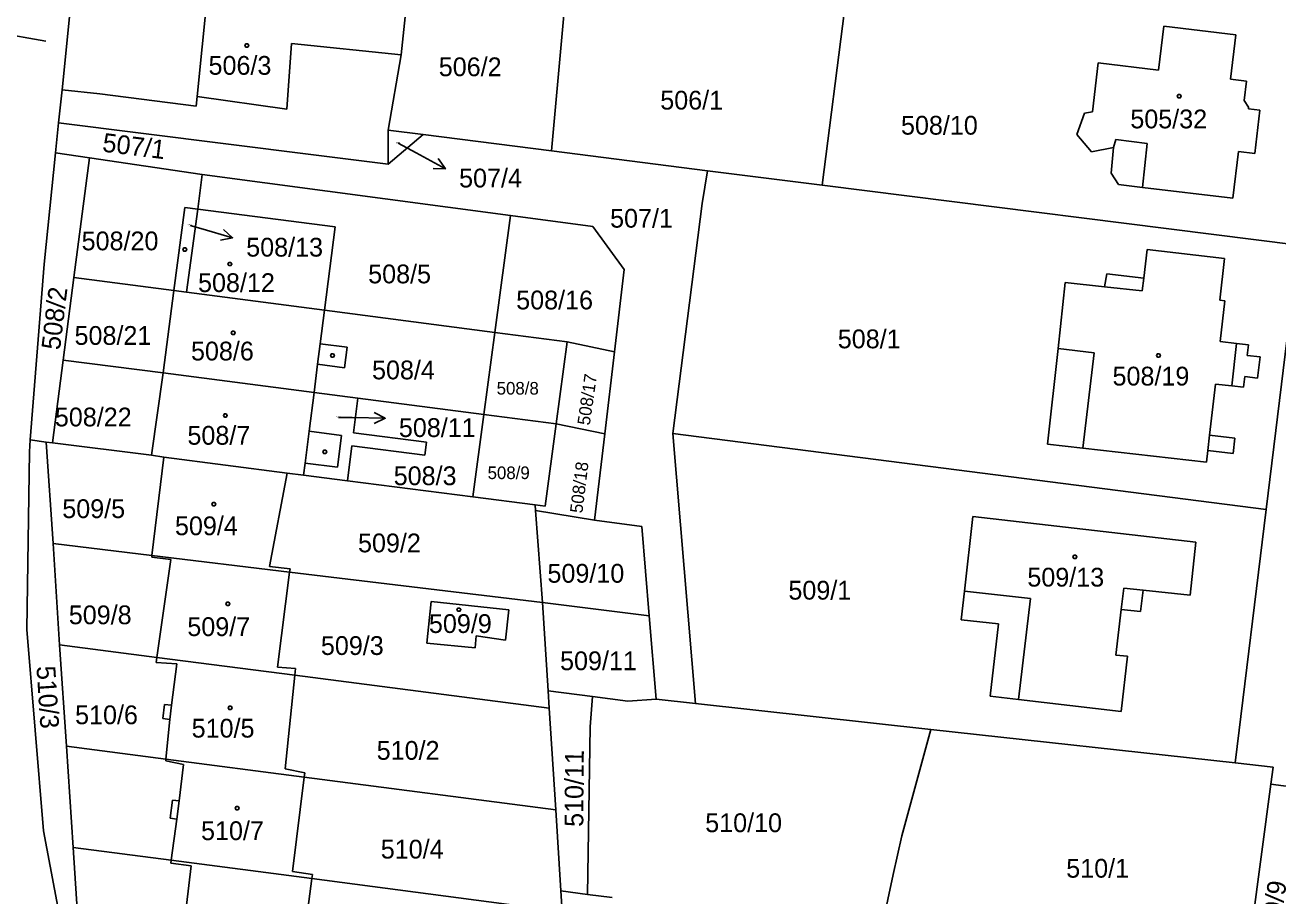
# Model space of a CAD drawing. Extents: x -639590 to -639298, y -1193269 to -1192863.
# Drawn here: x -639509.2 to -639395.8, y -1192995.4 to -1192916.5 of the extents above; entities that cross this region are included whole.
import ezdxf

# ---------------------------------------------------------------- set-up
doc = ezdxf.new("R2010")
doc.units = 0
for name, color, linetype in [('Vrstva 1', 7, 'Continuous'), ('Vrstva 2', 7, 'Continuous'), ('Vrstva 25', 7, 'Continuous'), ('Vrstva 4', 7, 'Continuous'), ('Vrstva 5', 7, 'Continuous'), ('Vrstva 7', 7, 'Continuous')]:
    doc.layers.add(name, color=color, linetype=linetype)

msp = doc.modelspace()

# ---------------------------------------------------------------- linework, layer by layer
at = {"layer": 'Vrstva 1'}
for p, q in [((-639504.16, -1192906.23), (-639505.82, -1192922.39)), ((-639461.52, -1192927.91), (-639460.05, -1192911.94)), ((-639492.68, -1192913.98), (-639493.6, -1192922.99)), ((-639475.12, -1192919.21), (-639474.65, -1192914.63)), ((-639434.99, -1192915.19), (-639437.01, -1192931.02)), ((-639406.1, -1192916.63), (-639406.58, -1192920.61)), ((-639399.58, -1192917.41), (-639406.1, -1192916.63)), ((-639400.06, -1192921.43), (-639399.58, -1192917.41)), ((-639475.12, -1192919.21), (-639476.29, -1192926.03)), ((-639412.03, -1192919.95), (-639412.54, -1192924.38)), ((-639406.58, -1192920.61), (-639412.03, -1192919.95)), ((-639398.59, -1192921.61), (-639400.06, -1192921.43)), ((-639398.8, -1192923.34), (-639398.59, -1192921.61)), ((-639505.82, -1192922.39), (-639506.13, -1192925.38)), ((-639505.82, -1192922.39), (-639502.41, -1192922.75)), ((-639502.41, -1192922.75), (-639493.69, -1192923.85)), ((-639493.69, -1192923.85), (-639493.6, -1192922.99)), ((-639398.41, -1192923.95), (-639398.8, -1192923.34)), ((-639398.43, -1192924.1), (-639398.41, -1192923.95)), ((-639413.28, -1192924.5), (-639413.96, -1192926.43)), ((-639412.54, -1192924.38), (-639413.28, -1192924.5)), ((-639397.39, -1192924.22), (-639398.43, -1192924.1)), ((-639397.86, -1192928.14), (-639397.39, -1192924.22)), ((-639506.13, -1192925.38), (-639506.41, -1192928.09)), ((-639506.13, -1192925.38), (-639483.29, -1192928.23)), ((-639476.29, -1192926.03), (-639476.3, -1192929.1)), ((-639476.29, -1192926.03), (-639473.13, -1192926.43)), ((-639476.3, -1192929.1), (-639473.13, -1192926.43)), ((-639473.13, -1192926.43), (-639461.52, -1192927.91)), ((-639413.96, -1192926.43), (-639412.64, -1192928)), ((-639506.41, -1192928.09), (-639507.43, -1192938.15)), ((-639506.41, -1192928.09), (-639503.33, -1192928.54)), ((-639483.29, -1192928.23), (-639476.3, -1192929.1)), ((-639461.52, -1192927.91), (-639447.4, -1192929.71)), ((-639412.64, -1192928), (-639410.64, -1192927.59)), ((-639410.64, -1192927.59), (-639410.84, -1192929.94)), ((-639399.85, -1192932.18), (-639399.34, -1192927.96)), ((-639399.34, -1192927.96), (-639397.86, -1192928.14)), ((-639503.33, -1192928.54), (-639504.74, -1192939.37)), ((-639493.13, -1192930.04), (-639503.33, -1192928.54)), ((-639493.54, -1192933.18), (-639493.13, -1192930.04)), ((-639493.13, -1192930.04), (-639465.22, -1192933.76)), ((-639447.88, -1192932.66), (-639447.4, -1192929.71)), ((-639437.01, -1192931.02), (-639447.4, -1192929.71)), ((-639410.84, -1192929.94), (-639410.19, -1192930.95)), ((-639393.89, -1192936.45), (-639437.01, -1192931.02)), ((-639410.19, -1192930.95), (-639408.01, -1192931.21)), ((-639408.01, -1192931.21), (-639399.85, -1192932.18)), ((-639495.71, -1192940.54), (-639494.72, -1192933.03)), ((-639494.72, -1192933.03), (-639493.54, -1192933.18)), ((-639450.53, -1192953.5), (-639447.88, -1192932.66)), ((-639494.57, -1192940.69), (-639493.54, -1192933.18)), ((-639493.54, -1192933.18), (-639481.11, -1192934.79)), ((-639466.65, -1192944.34), (-639465.22, -1192933.76)), ((-639465.22, -1192933.76), (-639457.78, -1192934.75)), ((-639481.11, -1192934.79), (-639482.07, -1192942.33)), ((-639457.78, -1192934.75), (-639454.93, -1192938.64)), ((-639393.89, -1192936.45), (-639396.82, -1192960.36)), ((-639407.58, -1192936.84), (-639407.89, -1192939.43)), ((-639400.58, -1192937.64), (-639407.58, -1192936.84)), ((-639507.43, -1192938.15), (-639508.7, -1192954.08)), ((-639454.93, -1192938.64), (-639455.81, -1192946.09)), ((-639401.01, -1192941.42), (-639400.58, -1192937.64)), ((-639504.74, -1192939.37), (-639505.71, -1192946.84)), ((-639504.74, -1192939.37), (-639495.71, -1192940.54)), ((-639415.02, -1192939.83), (-639415.66, -1192945.81)), ((-639411.45, -1192940.22), (-639415.02, -1192939.83)), ((-639411.26, -1192939.05), (-639411.45, -1192940.22)), ((-639407.89, -1192939.43), (-639411.26, -1192939.05)), ((-639496.66, -1192948), (-639495.71, -1192940.54)), ((-639495.71, -1192940.54), (-639494.57, -1192940.69)), ((-639494.57, -1192940.69), (-639482.07, -1192942.33)), ((-639400.57, -1192941.47), (-639401.01, -1192941.42)), ((-639400.99, -1192945.17), (-639400.57, -1192941.47)), ((-639482.07, -1192942.33), (-639482.46, -1192945.37)), ((-639482.07, -1192942.33), (-639466.65, -1192944.34)), ((-639467.65, -1192951.78), (-639466.65, -1192944.34)), ((-639460.11, -1192945.19), (-639466.65, -1192944.34)), ((-639480, -1192945.68), (-639482.46, -1192945.37)), ((-639461.1, -1192952.63), (-639460.11, -1192945.19)), ((-639460.11, -1192945.19), (-639455.81, -1192946.09)), ((-639399.5, -1192945.34), (-639400.99, -1192945.17)), ((-639398.43, -1192945.46), (-639399.5, -1192945.34)), ((-639398.54, -1192946.42), (-639398.43, -1192945.46)), ((-639480, -1192945.68), (-639480.24, -1192947.55)), ((-639455.81, -1192946.09), (-639456.69, -1192953.53)), ((-639415.66, -1192945.81), (-639416.62, -1192954.46)), ((-639397.38, -1192946.56), (-639398.54, -1192946.42)), ((-639397.6, -1192948.47), (-639397.38, -1192946.56)), ((-639505.71, -1192946.84), (-639506.68, -1192954.34)), ((-639505.71, -1192946.84), (-639496.66, -1192948)), ((-639482.69, -1192947.23), (-639483.01, -1192949.78)), ((-639480.24, -1192947.55), (-639482.69, -1192947.23)), ((-639497.71, -1192955.46), (-639496.66, -1192948)), ((-639496.66, -1192948), (-639483.01, -1192949.78)), ((-639398.87, -1192949.31), (-639398.76, -1192948.34)), ((-639398.76, -1192948.34), (-639397.6, -1192948.47)), ((-639483.01, -1192949.78), (-639483.45, -1192953.28)), ((-639483.01, -1192949.78), (-639479.04, -1192950.3)), ((-639401.94, -1192953.65), (-639401.41, -1192949.02)), ((-639401.41, -1192949.02), (-639399.93, -1192949.19)), ((-639399.93, -1192949.19), (-639398.87, -1192949.31)), ((-639479.04, -1192950.3), (-639479.44, -1192953.44)), ((-639479.04, -1192950.3), (-639467.65, -1192951.78)), ((-639468.65, -1192959.23), (-639467.65, -1192951.78)), ((-639461.1, -1192952.63), (-639467.65, -1192951.78)), ((-639480.51, -1192953.66), (-639483.45, -1192953.28)), ((-639479.44, -1192953.44), (-639472.84, -1192954.29)), ((-639462.1, -1192960.08), (-639461.1, -1192952.63)), ((-639461.1, -1192952.63), (-639456.69, -1192953.53)), ((-639508.7, -1192954.08), (-639508.78, -1192955.14)), ((-639507.25, -1192954.27), (-639508.7, -1192954.08)), ((-639506.64, -1192963.45), (-639507.25, -1192954.27)), ((-639507.25, -1192954.27), (-639506.68, -1192954.34)), ((-639506.68, -1192954.34), (-639497.71, -1192955.46)), ((-639480.51, -1192953.66), (-639480.88, -1192956.55)), ((-639479.59, -1192954.6), (-639479.99, -1192957.77)), ((-639479.59, -1192954.6), (-639472.99, -1192955.45)), ((-639472.84, -1192954.29), (-639472.99, -1192955.45)), ((-639456.69, -1192953.53), (-639457.61, -1192961.33)), ((-639396.82, -1192960.36), (-639450.53, -1192953.5)), ((-639450.53, -1192953.5), (-639448.49, -1192977.92)), ((-639416.62, -1192954.46), (-639413.41, -1192954.82)), ((-639399.65, -1192953.91), (-639401.94, -1192953.65)), ((-639399.81, -1192955.3), (-639399.65, -1192953.91)), ((-639508.78, -1192955.14), (-639509.02, -1192971.25)), ((-639497.71, -1192955.46), (-639496.62, -1192955.64)), ((-639496.62, -1192955.64), (-639497.68, -1192964.53)), ((-639496.62, -1192955.64), (-639485.45, -1192957.07)), ((-639413.41, -1192954.82), (-639402.21, -1192956.09)), ((-639402.21, -1192956.09), (-639402.09, -1192955.04)), ((-639402.09, -1192955.04), (-639399.81, -1192955.3)), ((-639483.82, -1192956.18), (-639483.96, -1192957.26)), ((-639480.88, -1192956.55), (-639483.82, -1192956.18)), ((-639485.45, -1192957.07), (-639487.03, -1192965.52)), ((-639485.45, -1192957.07), (-639483.96, -1192957.26)), ((-639483.96, -1192957.26), (-639479.99, -1192957.77)), ((-639479.99, -1192957.77), (-639468.65, -1192959.23)), ((-639468.65, -1192959.23), (-639463, -1192959.96)), ((-639463, -1192959.96), (-639462.96, -1192960.46)), ((-639463, -1192959.96), (-639462.1, -1192960.08)), ((-639462.96, -1192960.46), (-639462.33, -1192968.8)), ((-639457.61, -1192961.33), (-639462.96, -1192960.46)), ((-639453.34, -1192961.9), (-639457.61, -1192961.33)), ((-639423.39, -1192961), (-639424.14, -1192967.77)), ((-639403.2, -1192963.32), (-639423.39, -1192961)), ((-639399.63, -1192983.32), (-639396.82, -1192960.36)), ((-639452.66, -1192969.99), (-639453.34, -1192961.9)), ((-639506.04, -1192972.62), (-639506.64, -1192963.45)), ((-639497.68, -1192964.53), (-639506.64, -1192963.45)), ((-639403.7, -1192968.14), (-639403.2, -1192963.32)), ((-639497.68, -1192964.53), (-639497.7, -1192964.68)), ((-639495.97, -1192964.89), (-639497.7, -1192964.68)), ((-639485.22, -1192966.04), (-639497.68, -1192964.53)), ((-639497.23, -1192973.76), (-639495.97, -1192964.89)), ((-639487.03, -1192965.52), (-639485.18, -1192965.75)), ((-639485.18, -1192965.75), (-639485.22, -1192966.04)), ((-639485.22, -1192966.04), (-639486.31, -1192974.64)), ((-639462.33, -1192968.8), (-639485.22, -1192966.04)), ((-639424.14, -1192967.77), (-639424.43, -1192970.35)), ((-639408.21, -1192969.62), (-639407.96, -1192967.68)), ((-639407.96, -1192967.68), (-639403.7, -1192968.14)), ((-639472.79, -1192972.46), (-639472.41, -1192968.71)), ((-639472.41, -1192968.71), (-639465.38, -1192969.47)), ((-639452.66, -1192969.99), (-639462.33, -1192968.8)), ((-639462.33, -1192968.8), (-639461.83, -1192976.78)), ((-639465.38, -1192969.47), (-639465.67, -1192972.19)), ((-639452.04, -1192977.53), (-639452.66, -1192969.99)), ((-639424.43, -1192970.35), (-639421.05, -1192970.72)), ((-639410.42, -1192973.55), (-639409.95, -1192969.42)), ((-639409.95, -1192969.42), (-639408.21, -1192969.62)), ((-639509.02, -1192971.25), (-639507.5, -1192989.45)), ((-639421.05, -1192970.72), (-639421.81, -1192977.28)), ((-639505.43, -1192981.79), (-639506.04, -1192972.62)), ((-639497.23, -1192973.76), (-639506.04, -1192972.62)), ((-639468.43, -1192972.89), (-639472.79, -1192972.46)), ((-639468.33, -1192971.82), (-639468.43, -1192972.89)), ((-639465.67, -1192972.19), (-639468.33, -1192971.82)), ((-639497.3, -1192974.23), (-639497.23, -1192973.76)), ((-639484.75, -1192975.37), (-639497.23, -1192973.76)), ((-639409.39, -1192973.64), (-639410.42, -1192973.55)), ((-639409.96, -1192978.65), (-639409.39, -1192973.64)), ((-639495.44, -1192974.33), (-639497.3, -1192974.23)), ((-639495.9, -1192978.09), (-639495.44, -1192974.33)), ((-639486.31, -1192974.64), (-639484.69, -1192974.77)), ((-639484.69, -1192974.77), (-639484.75, -1192975.37)), ((-639484.75, -1192975.37), (-639485.61, -1192983.86)), ((-639461.73, -1192978.35), (-639484.75, -1192975.37)), ((-639461.83, -1192976.78), (-639457.81, -1192977.3)), ((-639461.73, -1192978.35), (-639461.83, -1192976.78)), ((-639457.81, -1192977.3), (-639458.02, -1192980.06)), ((-639457.81, -1192977.3), (-639454.62, -1192977.71)), ((-639421.81, -1192977.28), (-639419.23, -1192977.58)), ((-639496.7, -1192979.3), (-639496.54, -1192978.02)), ((-639496.54, -1192978.02), (-639495.9, -1192978.09)), ((-639461.13, -1192987.55), (-639461.73, -1192978.35)), ((-639452.04, -1192977.53), (-639454.62, -1192977.71)), ((-639448.49, -1192977.92), (-639452.04, -1192977.53)), ((-639448.49, -1192977.92), (-639427.17, -1192980.28)), ((-639419.23, -1192977.58), (-639409.96, -1192978.65)), ((-639496.06, -1192979.38), (-639496.7, -1192979.3)), ((-639496.42, -1192982.96), (-639496.06, -1192979.38)), ((-639458.02, -1192980.06), (-639458.26, -1192995.21)), ((-639427.17, -1192980.28), (-639429.8, -1192989.92)), ((-639427.17, -1192980.28), (-639399.63, -1192983.32)), ((-639504.82, -1192990.96), (-639505.43, -1192981.79)), ((-639505.43, -1192981.79), (-639496.42, -1192982.96)), ((-639496.42, -1192982.96), (-639483.9, -1192984.59)), ((-639485.61, -1192983.86), (-639483.85, -1192984.2)), ((-639399.63, -1192983.32), (-639396.19, -1192983.7)), ((-639396.19, -1192983.7), (-639396.4, -1192985.25)), ((-639483.9, -1192984.59), (-639484.96, -1192993.13)), ((-639483.85, -1192984.2), (-639483.9, -1192984.59)), ((-639483.9, -1192984.59), (-639461.13, -1192987.55)), ((-639396.4, -1192985.25), (-639398.77, -1193003.07)), ((-639396.4, -1192985.25), (-639393.41, -1192985.63)), ((-639460.66, -1192994.89), (-639461.13, -1192987.55)), ((-639507.5, -1192989.45), (-639503.7, -1193009.43)), ((-639429.8, -1192989.92), (-639430.58, -1192993.42)), ((-639504.21, -1193000.14), (-639504.82, -1192990.96)), ((-639495.93, -1192992.12), (-639504.82, -1192990.96)), ((-639495.97, -1192992.38), (-639495.93, -1192992.12)), ((-639494.14, -1192992.64), (-639495.97, -1192992.38)), ((-639483.21, -1192993.78), (-639495.93, -1192992.12)), ((-639494.57, -1192996.2), (-639494.14, -1192992.64)), ((-639484.96, -1192993.13), (-639483.16, -1192993.4)), ((-639483.21, -1192993.78), (-639484.31, -1193002.34)), ((-639483.16, -1192993.4), (-639483.21, -1192993.78)), ((-639460.55, -1192996.75), (-639483.21, -1192993.78)), ((-639430.58, -1192993.42), (-639431.72, -1192998.71)), ((-639458.26, -1192995.21), (-639460.66, -1192994.89)), ((-639460.55, -1192996.75), (-639460.66, -1192994.89)), ((-639456.03, -1192995.5), (-639458.26, -1192995.21))]:
    msp.add_line(p, q, dxfattribs=at)
at = {"layer": 'Vrstva 25'}
msp.add_line((-639514.03, -1192916.81), (-639507.28, -1192917.98), dxfattribs=at)
at = {"layer": 'Vrstva 4'}
for p, q in [((-639485.46, -1192924.14), (-639485.05, -1192918.2)), ((-639485.05, -1192918.2), (-639475.12, -1192919.21)), ((-639493.6, -1192922.99), (-639485.46, -1192924.14)), ((-639410.42, -1192926.88), (-639410.64, -1192927.59)), ((-639407.59, -1192927.25), (-639410.42, -1192926.88)), ((-639408.01, -1192931.21), (-639407.59, -1192927.25)), ((-639408.04, -1192940.58), (-639407.89, -1192939.43)), ((-639411.45, -1192940.22), (-639408.04, -1192940.58)), ((-639482.46, -1192945.37), (-639482.69, -1192947.23)), ((-639399.5, -1192945.34), (-639399.93, -1192949.19)), ((-639415.66, -1192945.81), (-639412.39, -1192946.2)), ((-639412.39, -1192946.2), (-639413.41, -1192954.82)), ((-639483.45, -1192953.28), (-639483.82, -1192956.18)), ((-639401.94, -1192953.65), (-639402.09, -1192955.04)), ((-639424.14, -1192967.77), (-639418.17, -1192968.44)), ((-639409.95, -1192969.42), (-639409.72, -1192967.49)), ((-639409.72, -1192967.49), (-639407.96, -1192967.68)), ((-639418.17, -1192968.44), (-639419.23, -1192977.58)), ((-639496.06, -1192979.38), (-639495.9, -1192978.09)), ((-639496.44, -1192983.12), (-639496.42, -1192982.96)), ((-639494.82, -1192983.46), (-639496.44, -1192983.12)), ((-639495.22, -1192986.76), (-639494.82, -1192983.46)), ((-639496.02, -1192988.32), (-639495.82, -1192986.69)), ((-639495.82, -1192986.69), (-639495.22, -1192986.76)), ((-639495.42, -1192988.4), (-639495.22, -1192986.76)), ((-639495.42, -1192988.4), (-639496.02, -1192988.32)), ((-639495.93, -1192992.12), (-639495.42, -1192988.4))]:
    msp.add_line(p, q, dxfattribs=at)
at = {"layer": 'Vrstva 5'}
for points in [[(-639489.01, -1192918.22), (-639488.92, -1192918.37), (-639489.01, -1192918.52), (-639489.19, -1192918.52), (-639489.28, -1192918.37), (-639489.19, -1192918.22)], [(-639404.6, -1192922.82), (-639404.51, -1192922.97), (-639404.6, -1192923.12), (-639404.78, -1192923.12), (-639404.87, -1192922.97), (-639404.78, -1192922.82)], [(-639494.62, -1192936.7), (-639494.53, -1192936.85), (-639494.62, -1192937), (-639494.8, -1192937), (-639494.89, -1192936.85), (-639494.8, -1192936.7)], [(-639490.54, -1192938), (-639490.45, -1192938.15), (-639490.54, -1192938.3), (-639490.72, -1192938.3), (-639490.81, -1192938.15), (-639490.72, -1192938)], [(-639490.24, -1192944.24), (-639490.15, -1192944.39), (-639490.24, -1192944.54), (-639490.42, -1192944.54), (-639490.51, -1192944.39), (-639490.42, -1192944.24)], [(-639481.25, -1192946.27), (-639481.16, -1192946.42), (-639481.25, -1192946.57), (-639481.43, -1192946.57), (-639481.52, -1192946.42), (-639481.43, -1192946.27)], [(-639406.49, -1192946.28), (-639406.4, -1192946.43), (-639406.49, -1192946.58), (-639406.67, -1192946.58), (-639406.76, -1192946.43), (-639406.67, -1192946.28)], [(-639490.95, -1192951.7), (-639490.86, -1192951.85), (-639490.95, -1192952), (-639491.13, -1192952), (-639491.22, -1192951.85), (-639491.13, -1192951.7)], [(-639481.95, -1192955.01), (-639481.86, -1192955.16), (-639481.95, -1192955.31), (-639482.13, -1192955.31), (-639482.22, -1192955.16), (-639482.13, -1192955.01)], [(-639492, -1192959.74), (-639491.91, -1192959.89), (-639492, -1192960.04), (-639492.18, -1192960.04), (-639492.27, -1192959.89), (-639492.18, -1192959.74)], [(-639414.05, -1192964.52), (-639413.96, -1192964.67), (-639414.05, -1192964.82), (-639414.23, -1192964.82), (-639414.32, -1192964.67), (-639414.23, -1192964.52)], [(-639490.72, -1192968.75), (-639490.63, -1192968.9), (-639490.72, -1192969.05), (-639490.9, -1192969.05), (-639490.99, -1192968.9), (-639490.9, -1192968.75)], [(-639469.81, -1192969.29), (-639469.72, -1192969.44), (-639469.81, -1192969.59), (-639469.99, -1192969.59), (-639470.08, -1192969.44), (-639469.99, -1192969.29)], [(-639490.52, -1192978.18), (-639490.43, -1192978.33), (-639490.52, -1192978.48), (-639490.7, -1192978.48), (-639490.79, -1192978.33), (-639490.7, -1192978.18)], [(-639489.89, -1192987.26), (-639489.8, -1192987.41), (-639489.89, -1192987.56), (-639490.07, -1192987.56), (-639490.16, -1192987.41), (-639490.07, -1192987.26)]]:
    msp.add_lwpolyline(points, close=True, dxfattribs=at)
at = {"layer": 'Vrstva 7'}
for p, q in [((-639475.4, -1192927.22), (-639473.76, -1192928.1)), ((-639471.12, -1192929.52), (-639473.76, -1192928.1)), ((-639494.23, -1192934.66), (-639493.27, -1192934.94)), ((-639490.39, -1192935.78), (-639493.27, -1192934.94)), ((-639480.81, -1192952.04), (-639479.57, -1192952.06)), ((-639476.57, -1192952.11), (-639479.57, -1192952.06))]:
    msp.add_line(p, q, dxfattribs=at)
for points in [[(-639471.76, -1192928.61), (-639471.12, -1192929.52), (-639472.23, -1192929.49)], [(-639491.21, -1192935.02), (-639490.39, -1192935.78), (-639491.49, -1192935.98)], [(-639477.56, -1192951.59), (-639476.57, -1192952.11), (-639477.58, -1192952.59)]]:
    msp.add_lwpolyline(points, dxfattribs=at)

# ---------------------------------------------------------------- texts
at = {"layer": 'Vrstva 2'}
for s, height, p in [('506/3', 1.7, (-639492.56, -1192921.02)), ('506/2', 1.7, (-639471.72, -1192921.15)), ('506/1', 1.7, (-639451.67, -1192924.17)), ('508/10', 1.7, (-639429.88, -1192926.44)), ('505/32', 1.7, (-639409.12, -1192925.87)), ('507/4', 0.1, (-639475.6, -1192927.22)), ('507/1', 1.7, (-639456.21, -1192934.86)), ('508/20', 1.7, (-639504.05, -1192936.91)), ('508/13', 0.1, (-639494.46, -1192934.66)), ('508/5', 1.7, (-639478.11, -1192939.9)), ('508/12', 1.7, (-639493.51, -1192940.69)), ('508/16', 1.7, (-639464.71, -1192942.26)), ('508/21', 1.7, (-639504.69, -1192945.47)), ('508/1', 1.7, (-639435.6, -1192945.78)), ('508/6', 1.7, (-639494.15, -1192946.88)), ('508/4', 1.7, (-639477.76, -1192948.59)), ('508/19', 1.7, (-639410.73, -1192949.15)), ('508/8', 1.14, (-639466.48, -1192949.97)), ('508/22', 1.7, (-639506.47, -1192952.85)), ('508/11', 0.1, (-639481.02, -1192952.04)), ('508/7', 1.7, (-639494.47, -1192954.51)), ('508/3', 1.7, (-639475.8, -1192958.17)), ('508/9', 1.14, (-639467.3, -1192957.62)), ('509/5', 1.7, (-639505.8, -1192961.15)), ('509/4', 1.7, (-639495.6, -1192962.7)), ('509/2', 1.7, (-639479.03, -1192964.25)), ('509/10', 1.7, (-639461.88, -1192967)), ('509/13', 1.7, (-639418.44, -1192967.35)), ('509/1', 1.7, (-639440.07, -1192968.53)), ('509/8', 1.7, (-639505.21, -1192970.76)), ('509/7', 1.7, (-639494.48, -1192971.83)), ('509/9', 1.7, (-639472.61, -1192971.55)), ('509/3', 1.7, (-639482.39, -1192973.54)), ('509/11', 1.7, (-639460.74, -1192974.92)), ('510/6', 1.7, (-639504.64, -1192979.81)), ('510/5', 1.7, (-639494.09, -1192981.02)), ('510/2', 1.7, (-639477.34, -1192983.03)), ('510/7', 1.7, (-639493.24, -1192990.3)), ('510/10', 1.7, (-639447.6, -1192989.58)), ('510/4', 1.7, (-639476.97, -1192991.97)), ('510/1', 1.7, (-639414.92, -1192993.7))]:
    msp.add_text(s, height=height, dxfattribs=at).set_placement(p)
for s, height, rotation, p in [('507/1', 1.7, 352.9906, (-639502.23, -1192927.97)), ('508/2', 1.7, 83.0789, (-639506.01, -1192945.99)), ('508/17', 1.14, 81.6465, (-639458.06, -1192952.8)), ('508/18', 1.14, 83.0789, (-639458.72, -1192960.75)), ('510/3', 1.7, 273.7592, (-639508.14, -1192974.58)), ('510/11', 1.7, 89.5533, (-639458.64, -1192989.11)), ('510/9', 1.7, 81.1308, (-639395.83, -1192999.74))]:
    msp.add_text(s, height=height, rotation=rotation, dxfattribs=at).set_placement(p)
at = {"layer": 'Vrstva 7'}
for s, p in [('507/4', (-639469.88, -1192931.22)), ('508/13', (-639489.15, -1192937.48)), ('508/11', (-639475.33, -1192953.81))]:
    msp.add_text(s, height=1.7, dxfattribs=at).set_placement(p)

doc.saveas('drawing.dxf')
